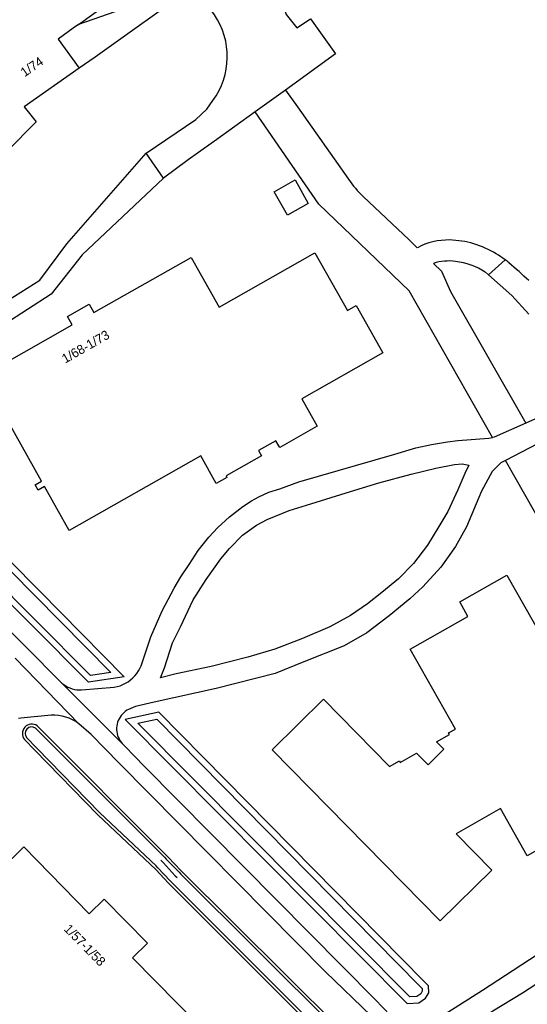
# Model space of a CAD drawing. Extents: x 162791 to 163827, y 385795 to 386523.
# Drawn here: x 162998.4 to 163053.2, y 386115 to 386221.3 of the extents above; entities that cross this region are included whole.
import ezdxf

# ---------------------------------------------------------------- set-up
doc = ezdxf.new("R2010")
doc.units = 0
for name, color, linetype in [('IMGEO_Duiker', 7, 'Continuous'), ('IMGEO_Erf', 7, 'Continuous'), ('IMGEO_Pand', 7, 'Continuous'), ('IMGEO_Pand_nummerreeks', 7, 'Continuous'), ('IMGEO_Waterloop', 7, 'Continuous'), ('IMGEO_Woonerf_gesloten', 7, 'Continuous'), ('IMGEO_Woonerf_open', 7, 'Continuous')]:
    doc.layers.add(name, color=color, linetype=linetype)

msp = doc.modelspace()

# ---------------------------------------------------------------- linework, layer by layer
at = {"layer": 'IMGEO_Duiker'}
msp.add_lwpolyline([(163013.61, 386130.55), (163013.86, 386130.28), (163015.18, 386128.85), (163015.37, 386128.65)], dxfattribs=at)
at = {"layer": 'IMGEO_Erf'}
for points in [[(163009.65, 386150.32), (163005.79, 386149.75), (162999.52, 386156.06), (162985.27, 386170.37), (162983.18, 386172.46), (162980.01, 386175.65), (162979.8, 386176.34), (162980.05, 386176.98), (162980.59, 386177.52), (162981.56, 386178.16), (162982.35, 386177.85), (162985.47, 386174.75), (162987.56, 386172.66), (163000.49, 386159.61), (163009.65, 386150.32)], [(163013.39, 386146.53), (163009.77, 386145.74), (163040.25, 386115.07), (163041.51, 386115.15), (163042.21, 386115.63), (163042.56, 386116.2), (163042.53, 386116.97), (163042.03, 386117.48), (163013.39, 386146.53)], [(162998.9, 386143.57), (163000, 386142.43), (163006.8, 386135.45), (163013.12, 386129.5), (163014.41, 386128.09), (163031.64, 386110.89), (163032.29, 386111.61), (163032.84, 386112.46), (163015.79, 386129.44), (163014.42, 386130.87), (163000.25, 386145.04)]]:
    msp.add_lwpolyline(points, dxfattribs=at)
msp.add_arc((162999.67, 386144.22), 1.01, 54.45, 220.6594, dxfattribs=at)
at = {"layer": 'IMGEO_Pand'}
for points in [[(163004.71, 386220.78), (163012.99, 386226.74), (163001.49, 386242.78)], [(163004.81, 386216.06), (162998.84, 386211.87), (163000, 386210.45), (163000.14, 386210.28), (162990.68, 386200.74), (162991.91, 386199.49), (162983.1, 386190.62), (162967.86, 386205.52), (162976.44, 386214.19), (162973.67, 386216.9), (162977.86, 386221.23), (162975.18, 386223.84)], [(163004.71, 386220.78), (163004.16, 386220.38), (163002.53, 386219.21), (163004.81, 386216.06)], [(163025.86, 386202.72), (163028.12, 386203.99), (163029.55, 386201.43), (163027.29, 386200.17), (163025.86, 386202.72)], [(162993.61, 386182.46), (163004.02, 386188.36), (163003.53, 386189.23), (163005.89, 386190.56), (163006.38, 386189.69), (163016.88, 386195.63), (163019.91, 386190.27), (163030.27, 386196.13), (163033.79, 386189.91), (163034.72, 386190.43), (163037.61, 386185.32), (163028.84, 386180.36), (163030.52, 386177.39), (163026.46, 386175.1), (163026.04, 386175.83), (163024.17, 386174.78), (163024.5, 386174.2), (163020.66, 386172.03), (163020.75, 386171.87), (163019.61, 386171.22), (163017.93, 386174.19)], [(163017.93, 386174.19), (163003.73, 386166.15), (163001.05, 386170.88), (163000.38, 386170.51), (163000.05, 386171.07), (163000.73, 386171.45), (162995.7, 386180.34)], [(163031.2, 386147.93), (163038.34, 386140.67), (163039.39, 386141.27), (163039.48, 386141.1), (163041.25, 386142.1), (163042.49, 386140.85), (163044.2, 386142.53), (163043.41, 386143.33), (163044.8, 386144.12), (163044.71, 386144.28), (163045.46, 386144.7), (163040.57, 386153.34), (163046.79, 386156.86), (163045.91, 386158.42), (163051.02, 386161.31), (163057.44, 386149.97)], [(163058.31, 386133.91), (163053.2, 386131.02), (163050.33, 386136.1), (163045.51, 386133.37), (163049.37, 386129.45), (163043.81, 386123.99), (163025.64, 386142.47), (163031.2, 386147.93)], [(162991.78, 386114.95), (162995.01, 386118.12), (162988.69, 386124.54), (162992.27, 386128.06), (162993.53, 386126.78), (162998.8, 386131.97), (163005.89, 386124.76), (163007.49, 386126.32), (163012.16, 386121.57), (163010.57, 386120), (163020.25, 386110.15)]]:
    msp.add_lwpolyline(points, dxfattribs=at)
at = {"layer": 'IMGEO_Waterloop'}
for points in [[(162984.99, 386174.27), (162987.08, 386172.18), (163000, 386159.13), (163008.22, 386150.8), (163006.03, 386150.48), (163000, 386156.54), (162985.75, 386170.85), (162983.67, 386172.94), (162980.61, 386176.01), (162980.52, 386176.31), (162980.64, 386176.6), (162981.02, 386176.99), (162981.64, 386177.4), (162981.97, 386177.27), (162984.99, 386174.27)], [(163041.54, 386117.01), (163041.86, 386116.68), (163041.87, 386116.38), (163041.7, 386116.11), (163041.27, 386115.81), (163040.52, 386115.77), (163011.13, 386145.34), (163013.17, 386145.78), (163041.54, 386117.01)], [(163000.06, 386144.81), (163014.01, 386130.86), (163014.21, 386130.65), (163015.58, 386129.23), (163015.78, 386129.02), (163032.46, 386112.42), (163032.05, 386111.79), (163031.63, 386111.32), (163014.83, 386128.09)], [(163014.83, 386128.09), (163014.63, 386128.3), (163013.31, 386129.71), (163013.11, 386129.92), (163007.01, 386135.66), (163000.21, 386142.64), (162999.12, 386143.77)]]:
    msp.add_lwpolyline(points, dxfattribs=at)
msp.add_arc((162999.67, 386144.22), 0.709, 56.2931, 220.0057, dxfattribs=at)
at = {"layer": 'IMGEO_Woonerf_gesloten'}
for points in [[(163003.46, 386244.2), (163014.83, 386228.27), (163009.48, 386222.44), (163004.71, 386220.78)], [(163019.15, 386235.48), (163020.73, 386235.26), (163024.94, 386229.66), (163025.83, 386226.03), (163027.16, 386221.87), (163028.3, 386220.43), (163029.8, 386221.38), (163032.5, 386217.6), (163027.08, 386213.7)], [(163019.42, 386221.83), (163017.21, 386224.9), (163006.51, 386217.25), (163004.81, 386216.06)], [(163027.08, 386213.7), (163023.81, 386211.35)], [(163012.04, 386206.87), (163017.41, 386210.52), (163018.58, 386211.64), (163019.24, 386212.57)], [(163023.81, 386211.35), (163019.41, 386208.18), (163019.29, 386208.1), (163017.67, 386206.96), (163016.57, 386206.18), (163013.89, 386204.2)], [(163013.89, 386204.2), (163012.04, 386206.87)], [(163050.81, 386195.37), (163049.01, 386193.75)], [(163049.01, 386193.75), (163051.56, 386191.53), (163053.38, 386189.5)], [(163057.43, 386179.66), (163053.05, 386177.72)], [(163053.05, 386177.72), (163049.63, 386176.2), (163049.45, 386176.18)], [(163002.73, 386149.83), (163002.92, 386149.65), (163003.12, 386149.5), (163003.34, 386149.35), (163003.57, 386149.23), (163003.8, 386149.13), (163004.04, 386149.05), (163004.29, 386148.98), (163004.55, 386148.94), (163004.8, 386148.92), (163005.06, 386148.92), (163008.58, 386149.21), (163008.9, 386149.28), (163009.21, 386149.38), (163009.51, 386149.49), (163009.8, 386149.64), (163010.08, 386149.81), (163010.34, 386150), (163010.59, 386150.21), (163010.81, 386150.45), (163011.02, 386150.7), (163011.2, 386150.97), (163011.36, 386151.25), (163011.5, 386151.54), (163011.61, 386151.85), (163011.7, 386152.16), (163012.53, 386154.64), (163013.77, 386157.48), (163015.07, 386159.9), (163015.79, 386161.15), (163016.67, 386162.47), (163017.65, 386163.98), (163018.8, 386165.4), (163019.78, 386166.46), (163021.02, 386167.61), (163022.47, 386168.74), (163023.43, 386169.33), (163024.21, 386169.77), (163025.29, 386170.27), (163026.48, 386170.64), (163028.54, 386171.39), (163038.91, 386174.39), (163041.16, 386175.06), (163042.87, 386175.44), (163044.58, 386175.72), (163045.69, 386175.87), (163049.05, 386176.12), (163049.45, 386176.18)], [(163054.33, 386175.48), (163050.86, 386173.7)], [(163050.86, 386173.7), (163050.36, 386173.44), (163049.42, 386172.51), (163048.28, 386170.39), (163046.66, 386166.52), (163045.46, 386164.41), (163043.87, 386162.17), (163041.93, 386160.04), (163040.51, 386158.77), (163038.3, 386156.92), (163035.87, 386155.07), (163033.41, 386153.7), (163029.06, 386151.95), (163025.97, 386150.69), (163019.61, 386149.06), (163012.88, 386147.61), (163010.89, 386147.12), (163010.11, 386146.82), (163009.93, 386146.72), (163009.77, 386146.6), (163009.61, 386146.46), (163009.46, 386146.32), (163009.33, 386146.16), (163009.21, 386145.99), (163009.11, 386145.81), (163009.02, 386145.63), (163008.95, 386145.43), (163008.9, 386145.23), (163008.86, 386145.03), (163008.84, 386144.83), (163008.84, 386144.62), (163008.86, 386144.42), (163008.89, 386144.21), (163008.94, 386144.01), (163009.01, 386143.82), (163009.1, 386143.63), (163009.2, 386143.45), (163009.32, 386143.28), (163009.45, 386143.12)], [(163046.9, 386173.2), (163046.46, 386172.28), (163045.7, 386170.52), (163044.61, 386168.2), (163043.64, 386166.58), (163042.42, 386164.56), (163040.91, 386162.56), (163039.28, 386160.93), (163037.51, 386159.44), (163035.93, 386158.22), (163034.1, 386156.97), (163031.87, 386155.73), (163028.93, 386154.47), (163025.93, 386153.34), (163023.01, 386152.46), (163019.06, 386151.44), (163015.29, 386150.65), (163013.59, 386150.24), (163014.03, 386151.3), (163014.86, 386154), (163015.74, 386155.75), (163017.12, 386158.64), (163018.52, 386160.84), (163020.11, 386163.06), (163021.03, 386164.2), (163022.43, 386165.63), (163023.97, 386166.72), (163025.11, 386167.32), (163027.49, 386168.31), (163029.84, 386169.02), (163033.64, 386170.21), (163037.17, 386171.27), (163040.68, 386172.23), (163043.34, 386172.86), (163045.36, 386173.26), (163046.17, 386173.35), (163046.9, 386173.2)], [(163004.76, 386145.27), (162997.88, 386152.34)], [(163002.73, 386149.83), (163009.45, 386143.12)], [(163004.76, 386145.27), (163004.43, 386145.5), (163004.08, 386145.69), (163003.71, 386145.86), (163003.34, 386145.99), (163002.95, 386146.09), (163002.55, 386146.15), (163002.15, 386146.18), (163001.76, 386146.18), (162998.48, 386145.88), (162998.22, 386145.84)], [(163038.43, 386113.76), (163038.84, 386113.54), (163039.27, 386113.34), (163039.71, 386113.19), (163040.16, 386113.08), (163040.62, 386113.02), (163041.09, 386112.99), (163041.55, 386113.01), (163042.01, 386113.07), (163042.47, 386113.17), (163044.33, 386113.93), (163048.38, 386116.51), (163055.95, 386121.44), (163058.68, 386123.89), (163060.17, 386125.34), (163064.9, 386130.13), (163071.55, 386137.29)], [(163073.09, 386135.24), (163062.74, 386124.27), (163061.15, 386122.84), (163057.04, 386119.12), (163054.85, 386117.59), (163052.69, 386116.17), (163049.48, 386114.23), (163046.01, 386112.24), (163042.01, 386110.03)]]:
    msp.add_lwpolyline(points, dxfattribs=at)
for centre, radius, start, end in [((163012.77, 386217.32), 8.03, 323.683, 34.1771), ((163044.12, 386186.34), 11.24, 50.7111, 53.4835), ((163015.76, 386153.24), 54.82, 46.6674, 49.6829)]:
    msp.add_arc(centre, radius, start, end, dxfattribs=at)
at = {"layer": 'IMGEO_Woonerf_open'}
for points in [[(163027.08, 386213.7), (163028.38, 386211.87), (163033.88, 386204.08)], [(163049.45, 386176.18), (163040.44, 386192.01), (163030.69, 386201.39), (163023.81, 386211.35)], [(162978.92, 386179.77), (162983.54, 386182.64), (162989.55, 386186.25), (163000.56, 386193.16), (163003.46, 386197.1), (163012.04, 386206.87)], [(163013.89, 386204.2), (163005.12, 386195.91), (163001.75, 386191.66), (162991.5, 386185.05), (162983.2, 386179.88), (162976.87, 386175.9), (163002.73, 386149.83)], [(163035.49, 386202.19), (163040.44, 386197.51), (163041.33, 386196.66)], [(163043.08, 386194.98), (163043.96, 386194.14), (163044.9, 386191.93), (163053.05, 386177.72)], [(163049.01, 386193.75), (163048.68, 386194.04)], [(163071.55, 386137.29), (163071.46, 386137.47), (163050.86, 386173.7)], [(163036.33, 386113.74), (163031.42, 386118.47), (163009.12, 386141.02), (163006.09, 386144.1), (163004.76, 386145.27)], [(163009.45, 386143.12), (163009.59, 386142.98), (163009.74, 386142.84), (163011.85, 386140.66), (163036.77, 386115.49), (163038.43, 386113.76)]]:
    msp.add_lwpolyline(points, dxfattribs=at)
for centre, radius, start, end in [((163044.2, 386211.24), 12.56, 214.7375, 226.0899), ((163044.73, 386190.27), 7.24, 89.3318, 117.9722), ((163044.56, 386187.41), 10.1, 58.3913, 88.5837), ((163044.74, 386189.68), 5.56, 82.59, 107.4035), ((163044.67, 386187.92), 7.31, 56.7547, 83.7888), ((163043.71, 386185.76), 11.95, 53.5768, 59.0708)]:
    msp.add_arc(centre, radius, start, end, dxfattribs=at)

# ---------------------------------------------------------------- texts
at = {"layer": 'IMGEO_Pand_nummerreeks'}
for s, rotation, p in [('1/74', 34.5337, (162998.89, 386215.07)), ('1/68-1/73', 29.8512, (163003.28, 386184.15)), ('1/57-1/58', 314.5275, (163003.07, 386123.03))]:
    msp.add_text(s, height=1, rotation=rotation, dxfattribs=at).set_placement(p)

doc.saveas('drawing.dxf')
